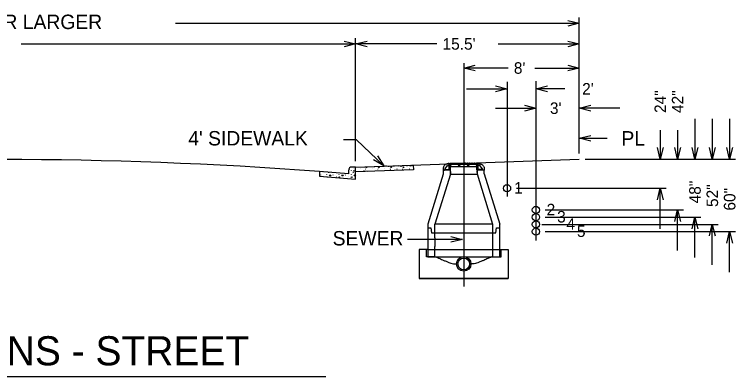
# Model space of a CAD drawing. Extents: x 524397 to 525117, y 3701341 to 3701821.
# Drawn here: x 524804 to 524903.9, y 3701401.1 to 3701451.2 of the extents above; entities that cross this region are included whole.
import ezdxf

# ---------------------------------------------------------------- set-up
doc = ezdxf.new("R2010")
doc.units = 0
doc.layers.add('Level 1', color=7, linetype='Continuous')
doc.layers.add('Level 11', color=7, linetype='Continuous')

msp = doc.modelspace()

# ---------------------------------------------------------------- linework, layer by layer
at = {"layer": 'Level 1'}
msp.add_line((524757.469, 3701401.064), (524847.188, 3701401.064), dxfattribs=at)
at = {"layer": 'Level 11'}
for p, q in [((524882.269, 3701431.982), (524882.269, 3701450.815)), ((524826.327, 3701450.014), (524882.269, 3701450.014)), ((524880.668, 3701450.415), (524882.269, 3701450.014)), ((524882.269, 3701450.014), (524880.668, 3701449.614)), ((524851.288, 3701430.9), (524851.288, 3701447.958)), ((524882.269, 3701431.982), (524882.269, 3701447.958)), ((524804.941, 3701447.157), (524851.288, 3701447.157)), ((524849.687, 3701447.557), (524851.288, 3701447.157)), ((524851.288, 3701447.157), (524849.687, 3701446.757)), ((524851.288, 3701447.157), (524852.889, 3701447.557)), ((524862.537, 3701447.157), (524851.288, 3701447.157)), ((524852.889, 3701446.757), (524851.288, 3701447.157)), ((524871.02, 3701447.157), (524882.269, 3701447.157)), ((524880.668, 3701447.557), (524882.269, 3701447.157)), ((524882.269, 3701447.157), (524880.668, 3701446.757)), ((524866.269, 3701444.489), (524866.269, 3701413.524)), ((524866.269, 3701443.819), (524867.87, 3701444.219)), ((524872.41, 3701443.819), (524866.269, 3701443.819)), ((524867.87, 3701443.418), (524866.269, 3701443.819)), ((524876.128, 3701443.819), (524882.269, 3701443.819)), ((524880.668, 3701444.219), (524882.269, 3701443.819)), ((524882.269, 3701443.819), (524880.668, 3701443.418)), ((524872.269, 3701441.919), (524872.269, 3701426.037)), ((524876.269, 3701441.988), (524876.269, 3701419.918)), ((524866.666, 3701440.933), (524872.269, 3701440.933)), ((524870.668, 3701441.334), (524872.269, 3701440.933)), ((524872.269, 3701440.933), (524870.668, 3701440.533)), ((524876.269, 3701440.933), (524877.87, 3701441.334)), ((524880.272, 3701440.933), (524876.269, 3701440.933)), ((524877.87, 3701440.533), (524876.269, 3701440.933)), ((524870.666, 3701438.254), (524876.269, 3701438.254)), ((524874.668, 3701438.654), (524876.269, 3701438.254)), ((524876.269, 3701438.254), (524874.668, 3701437.854)), ((524882.269, 3701438.254), (524883.87, 3701438.654)), ((524887.873, 3701438.254), (524882.269, 3701438.254)), ((524883.87, 3701437.854), (524882.269, 3701438.254)), ((524898.302, 3701436.785), (524898.302, 3701431.182)), ((524900.703, 3701436.785), (524900.703, 3701431.182)), ((524903.105, 3701436.785), (524903.105, 3701431.182)), ((524893.499, 3701435.185), (524893.499, 3701431.182)), ((524895.9, 3701435.185), (524895.9, 3701431.182)), ((524851.416, 3701433.875), (524849.611, 3701433.875)), ((524855.195, 3701430.264), (524851.416, 3701433.875)), ((524882.269, 3701434.088), (524883.87, 3701434.488)), ((524882.269, 3701434.088), (524886.145, 3701434.088)), ((524883.87, 3701433.688), (524882.269, 3701434.088)), ((524893.499, 3701431.182), (524893.099, 3701432.783)), ((524893.899, 3701432.783), (524893.499, 3701431.182)), ((524895.9, 3701431.182), (524895.5, 3701432.783)), ((524896.301, 3701432.783), (524895.9, 3701431.182)), ((524898.302, 3701431.182), (524897.902, 3701432.783)), ((524898.702, 3701432.783), (524898.302, 3701431.182)), ((524900.703, 3701431.182), (524900.303, 3701432.783)), ((524901.103, 3701432.783), (524900.703, 3701431.182)), ((524903.105, 3701431.182), (524902.704, 3701432.783)), ((524903.505, 3701432.783), (524903.105, 3701431.182)), ((524851.288, 3701430.099), (524882.269, 3701431.182)), ((524855.195, 3701430.264), (524853.761, 3701431.081)), ((524854.314, 3701431.66), (524855.195, 3701430.264)), ((524883.07, 3701431.182), (524894.299, 3701431.182)), ((524883.07, 3701431.182), (524896.701, 3701431.182)), ((524883.07, 3701431.182), (524899.102, 3701431.182)), ((524883.07, 3701431.182), (524901.504, 3701431.182)), ((524883.07, 3701431.182), (524903.905, 3701431.182)), ((524851.288, 3701430.099), (524850.775, 3701430.099)), ((524850.775, 3701430.099), (524850.788, 3701430.099)), ((524850.994, 3701429.886), (524851.008, 3701429.918)), ((524851.288, 3701430.099), (524859.283, 3701430.379)), ((524851.288, 3701428.438), (524851.288, 3701430.099)), ((524851.288, 3701429.439), (524851.288, 3701430.099)), ((524851.921, 3701429.833), (524851.935, 3701429.865)), ((524852.444, 3701430.14), (524852.445, 3701430.124)), ((524852.684, 3701429.833), (524852.698, 3701429.812)), ((524852.698, 3701429.825), (524852.713, 3701429.804)), ((524853.622, 3701429.833), (524853.636, 3701429.865)), ((524854.143, 3701430.156), (524854.147, 3701430.124)), ((524854.386, 3701429.833), (524854.4, 3701429.812)), ((524854.4, 3701429.825), (524854.414, 3701429.804)), ((524855.324, 3701429.833), (524855.338, 3701429.865)), ((524855.845, 3701430.156), (524855.848, 3701430.124)), ((524856.087, 3701429.833), (524856.101, 3701429.812)), ((524856.101, 3701429.825), (524856.116, 3701429.804)), ((524856.702, 3701430.245), (524856.716, 3701430.277)), ((524857.025, 3701429.833), (524857.039, 3701429.865)), ((524857.546, 3701430.156), (524857.55, 3701430.124)), ((524857.789, 3701429.833), (524857.803, 3701429.812)), ((524857.803, 3701429.825), (524857.817, 3701429.804)), ((524858.403, 3701430.245), (524858.417, 3701430.277)), ((524858.727, 3701429.833), (524858.741, 3701429.865)), ((524859.248, 3701430.156), (524859.251, 3701430.124)), ((524859.283, 3701430.379), (524859.306, 3701429.719)), ((524863.604, 3701429.665), (524863.604, 3701429.748)), ((524863.604, 3701429.748), (524863.687, 3701429.748)), ((524863.687, 3701429.748), (524863.688, 3701429.853)), ((524863.687, 3701429.748), (524864.27, 3701429.748)), ((524863.688, 3701429.853), (524864.037, 3701430.29)), ((524864.037, 3701430.29), (524864.27, 3701430.29)), ((524864.27, 3701430.581), (524864.27, 3701430.581)), ((524864.27, 3701430.581), (524864.354, 3701430.581)), ((524864.27, 3701430.29), (524864.27, 3701430.581)), ((524864.27, 3701429.748), (524864.27, 3701430.29)), ((524864.354, 3701430.165), (524864.354, 3701430.581)), ((524864.437, 3701430.165), (524864.354, 3701430.165)), ((524864.395, 3701430.581), (524864.395, 3701430.165)), ((524864.438, 3701430.581), (524864.395, 3701430.581)), ((524864.395, 3701430.581), (524864.438, 3701430.581)), ((524864.395, 3701430.165), (524864.395, 3701430.581)), ((524864.395, 3701430.165), (524868.142, 3701430.165)), ((524864.437, 3701430.165), (524864.395, 3701430.165)), ((524864.437, 3701430.165), (524864.488, 3701430.456)), ((524864.488, 3701430.456), (524864.437, 3701430.165)), ((524864.437, 3701429.665), (524864.437, 3701430.165)), ((524864.438, 3701430.581), (524864.453, 3701430.623)), ((524864.438, 3701430.581), (524864.453, 3701430.623)), ((524864.453, 3701430.623), (524864.515, 3701430.623)), ((524864.453, 3701430.623), (524864.515, 3701430.623)), ((524865.551, 3701430.456), (524864.488, 3701430.456)), ((524865.551, 3701430.456), (524864.488, 3701430.456)), ((524864.53, 3701430.581), (524864.515, 3701430.623)), ((524864.515, 3701430.623), (524864.53, 3701430.581)), ((524864.761, 3701430.581), (524864.53, 3701430.581)), ((524864.53, 3701430.581), (524864.761, 3701430.581)), ((524864.761, 3701430.581), (524864.777, 3701430.623)), ((524864.761, 3701430.581), (524864.777, 3701430.623)), ((524864.777, 3701430.623), (524864.836, 3701430.623)), ((524864.777, 3701430.623), (524864.836, 3701430.623)), ((524864.851, 3701430.581), (524864.836, 3701430.623)), ((524864.836, 3701430.623), (524864.851, 3701430.581)), ((524865.078, 3701430.581), (524864.851, 3701430.581)), ((524864.851, 3701430.581), (524865.078, 3701430.581)), ((524865.078, 3701430.581), (524865.093, 3701430.623)), ((524865.078, 3701430.581), (524865.093, 3701430.623)), ((524865.093, 3701430.623), (524865.16, 3701430.623)), ((524865.093, 3701430.623), (524865.16, 3701430.623)), ((524865.176, 3701430.581), (524865.16, 3701430.623)), ((524865.16, 3701430.623), (524865.176, 3701430.581)), ((524865.405, 3701430.581), (524865.176, 3701430.581)), ((524865.176, 3701430.581), (524865.405, 3701430.581)), ((524865.405, 3701430.581), (524865.42, 3701430.623)), ((524865.405, 3701430.581), (524865.42, 3701430.623)), ((524865.42, 3701430.623), (524865.485, 3701430.623)), ((524865.42, 3701430.623), (524865.485, 3701430.623)), ((524865.5, 3701430.581), (524865.485, 3701430.623)), ((524865.485, 3701430.623), (524865.5, 3701430.581)), ((524865.727, 3701430.581), (524865.5, 3701430.581)), ((524865.5, 3701430.581), (524865.727, 3701430.581)), ((524865.603, 3701430.165), (524865.551, 3701430.456)), ((524865.603, 3701430.165), (524865.551, 3701430.456)), ((524865.686, 3701430.165), (524865.603, 3701430.165)), ((524865.686, 3701430.165), (524865.738, 3701430.456)), ((524865.738, 3701430.456), (524865.686, 3701430.165)), ((524865.727, 3701430.581), (524865.743, 3701430.623)), ((524865.727, 3701430.581), (524865.743, 3701430.623)), ((524866.8, 3701430.456), (524865.738, 3701430.456)), ((524866.8, 3701430.456), (524865.738, 3701430.456)), ((524865.743, 3701430.623), (524865.801, 3701430.623)), ((524865.743, 3701430.623), (524865.801, 3701430.623)), ((524865.816, 3701430.581), (524865.801, 3701430.623)), ((524865.801, 3701430.623), (524865.816, 3701430.581)), ((524866.003, 3701430.581), (524865.816, 3701430.581)), ((524865.816, 3701430.581), (524866.003, 3701430.581)), ((524866.003, 3701430.581), (524866.018, 3701430.623)), ((524866.003, 3701430.581), (524866.018, 3701430.623)), ((524866.018, 3701430.623), (524866.269, 3701430.623)), ((524866.018, 3701430.623), (524866.52, 3701430.623)), ((524866.52, 3701430.623), (524866.269, 3701430.623)), ((524866.536, 3701430.581), (524866.52, 3701430.623)), ((524866.52, 3701430.623), (524866.536, 3701430.581)), ((524866.722, 3701430.581), (524866.536, 3701430.581)), ((524866.536, 3701430.581), (524866.722, 3701430.581)), ((524866.722, 3701430.581), (524866.737, 3701430.623)), ((524866.722, 3701430.581), (524866.737, 3701430.623)), ((524866.795, 3701430.623), (524866.737, 3701430.623)), ((524866.737, 3701430.623), (524866.795, 3701430.623)), ((524866.811, 3701430.581), (524866.795, 3701430.623)), ((524866.795, 3701430.623), (524866.811, 3701430.581)), ((524866.852, 3701430.165), (524866.8, 3701430.456)), ((524866.852, 3701430.165), (524866.8, 3701430.456)), ((524867.038, 3701430.581), (524866.811, 3701430.581)), ((524866.811, 3701430.581), (524867.038, 3701430.581)), ((524866.935, 3701430.165), (524866.852, 3701430.165)), ((524866.935, 3701430.165), (524866.986, 3701430.456)), ((524866.986, 3701430.456), (524866.935, 3701430.165)), ((524868.05, 3701430.456), (524866.986, 3701430.456)), ((524867.831, 3701430.456), (524866.986, 3701430.456)), ((524867.038, 3701430.581), (524867.053, 3701430.623)), ((524867.038, 3701430.581), (524867.053, 3701430.623)), ((524867.118, 3701430.623), (524867.053, 3701430.623)), ((524867.053, 3701430.623), (524867.118, 3701430.623)), ((524867.133, 3701430.581), (524867.118, 3701430.623)), ((524867.118, 3701430.623), (524867.133, 3701430.581)), ((524867.362, 3701430.581), (524867.133, 3701430.581)), ((524867.133, 3701430.581), (524867.362, 3701430.581)), ((524867.362, 3701430.581), (524867.377, 3701430.623)), ((524867.362, 3701430.581), (524867.377, 3701430.623)), ((524867.446, 3701430.623), (524867.377, 3701430.623)), ((524867.377, 3701430.623), (524867.446, 3701430.623)), ((524867.46, 3701430.581), (524867.446, 3701430.623)), ((524867.446, 3701430.623), (524867.46, 3701430.581)), ((524867.687, 3701430.581), (524867.46, 3701430.581)), ((524867.46, 3701430.581), (524867.687, 3701430.581)), ((524867.687, 3701430.581), (524867.702, 3701430.623)), ((524867.687, 3701430.581), (524867.702, 3701430.623)), ((524867.761, 3701430.623), (524867.702, 3701430.623)), ((524867.702, 3701430.623), (524867.761, 3701430.623)), ((524867.776, 3701430.581), (524867.761, 3701430.623)), ((524867.761, 3701430.623), (524867.776, 3701430.581)), ((524868.008, 3701430.581), (524867.776, 3701430.581)), ((524867.776, 3701430.581), (524867.831, 3701430.581)), ((524867.831, 3701430.581), (524867.831, 3701430.456)), ((524867.831, 3701430.581), (524867.831, 3701430.456)), ((524867.955, 3701430.581), (524867.955, 3701430.456)), ((524867.955, 3701430.581), (524868.008, 3701430.581)), ((524867.955, 3701430.456), (524867.955, 3701430.581)), ((524868.05, 3701430.456), (524867.955, 3701430.456)), ((524868.008, 3701430.581), (524868.023, 3701430.623)), ((524868.008, 3701430.581), (524868.023, 3701430.623)), ((524868.085, 3701430.623), (524868.023, 3701430.623)), ((524868.023, 3701430.623), (524868.085, 3701430.623)), ((524868.101, 3701430.165), (524868.05, 3701430.456)), ((524868.101, 3701430.165), (524868.05, 3701430.456)), ((524868.1, 3701430.581), (524868.085, 3701430.623)), ((524868.085, 3701430.623), (524868.1, 3701430.581)), ((524868.142, 3701430.581), (524868.1, 3701430.581)), ((524868.1, 3701430.581), (524868.142, 3701430.581)), ((524868.101, 3701429.665), (524868.101, 3701430.165)), ((524868.101, 3701430.165), (524868.184, 3701430.165)), ((524868.142, 3701430.165), (524868.101, 3701430.165)), ((524868.142, 3701430.581), (524868.142, 3701430.165)), ((524868.142, 3701430.581), (524868.142, 3701430.165)), ((524868.184, 3701430.165), (524868.184, 3701430.581)), ((524868.268, 3701430.581), (524868.184, 3701430.581)), ((524868.268, 3701430.29), (524868.268, 3701430.581)), ((524868.268, 3701429.748), (524868.268, 3701430.29)), ((524868.501, 3701430.29), (524868.268, 3701430.29)), ((524868.851, 3701429.748), (524868.268, 3701429.748)), ((524868.85, 3701429.853), (524868.501, 3701430.29)), ((524868.851, 3701429.748), (524868.85, 3701429.853)), ((524868.934, 3701429.748), (524868.851, 3701429.748)), ((524868.934, 3701429.665), (524868.934, 3701429.748)), ((524850.288, 3701429.175), (524846.288, 3701429.477)), ((524846.288, 3701429.477), (524846.288, 3701428.815)), ((524846.288, 3701428.815), (524851.288, 3701428.438)), ((524846.465, 3701428.983), (524846.479, 3701429.015)), ((524846.753, 3701429.328), (524846.767, 3701429.36)), ((524847.307, 3701429.065), (524847.321, 3701429.097)), ((524847.516, 3701429.328), (524847.53, 3701429.307)), ((524847.53, 3701429.32), (524847.545, 3701429.299)), ((524848.166, 3701428.983), (524848.181, 3701429.015)), ((524848.61, 3701428.756), (524848.625, 3701428.735)), ((524849.008, 3701429.065), (524849.022, 3701429.097)), ((524849.868, 3701428.983), (524849.882, 3701429.015)), ((524850.288, 3701429.637), (524850.288, 3701429.175)), ((524850.312, 3701428.756), (524850.326, 3701428.735)), ((524850.677, 3701429.651), (524850.68, 3701429.619)), ((524850.71, 3701429.065), (524850.724, 3701429.097)), ((524850.919, 3701429.328), (524850.933, 3701429.307)), ((524850.933, 3701429.32), (524850.948, 3701429.299)), ((524859.306, 3701429.719), (524851.288, 3701429.439)), ((524851.633, 3701429.488), (524851.647, 3701429.52)), ((524852.475, 3701429.57), (524852.489, 3701429.602)), ((524853.344, 3701429.511), (524853.349, 3701429.52)), ((524854.176, 3701429.57), (524854.19, 3701429.602)), ((524855.891, 3701429.6), (524855.892, 3701429.602)), ((524863.427, 3701429.132), (524861.276, 3701422.165)), ((524864.426, 3701429.132), (524862.276, 3701422.165)), ((524863.427, 3701429.665), (524863.427, 3701429.132)), ((524864.437, 3701429.665), (524863.427, 3701429.665)), ((524863.427, 3701429.665), (524863.604, 3701429.665)), ((524864.426, 3701429.132), (524864.426, 3701429.665)), ((524864.426, 3701429.499), (524864.426, 3701429.172)), ((524864.426, 3701429.132), (524868.112, 3701429.132)), ((524869.111, 3701429.665), (524868.101, 3701429.665)), ((524868.112, 3701429.665), (524868.112, 3701429.166)), ((524869.111, 3701429.665), (524868.112, 3701429.665)), ((524868.112, 3701429.332), (524868.112, 3701429.505)), ((524868.112, 3701429.166), (524870.271, 3701422.17)), ((524869.111, 3701429.665), (524868.934, 3701429.665)), ((524869.111, 3701429.166), (524869.111, 3701429.665)), ((524869.111, 3701429.166), (524871.271, 3701422.17)), ((524873.57, 3701427.152), (524894.299, 3701427.152)), ((524893.099, 3701425.551), (524893.499, 3701427.152)), ((524893.499, 3701421.548), (524893.499, 3701427.152)), ((524893.499, 3701427.152), (524893.899, 3701425.551)), ((524877.57, 3701424.152), (524896.701, 3701424.152)), ((524895.5, 3701422.551), (524895.9, 3701424.152)), ((524895.9, 3701418.548), (524895.9, 3701424.152)), ((524895.9, 3701424.152), (524896.301, 3701422.551)), ((524877.57, 3701423.152), (524899.102, 3701423.152)), ((524897.902, 3701421.551), (524898.302, 3701423.152)), ((524898.302, 3701417.548), (524898.302, 3701423.152)), ((524898.302, 3701423.152), (524898.702, 3701421.551)), ((524861.276, 3701422.165), (524861.276, 3701421.004)), ((524861.276, 3701421.872), (524861.276, 3701421.67)), ((524870.271, 3701422.169), (524862.276, 3701422.165)), ((524862.276, 3701421.004), (524862.276, 3701422.165)), ((524862.276, 3701421.67), (524862.276, 3701421.872)), ((524870.271, 3701422.17), (524870.271, 3701421.004)), ((524870.271, 3701422.17), (524870.271, 3701421.67)), ((524870.271, 3701421.872), (524870.271, 3701421.67)), ((524870.271, 3701421.872), (524870.271, 3701421.67)), ((524871.271, 3701421.67), (524871.271, 3701422.17)), ((524871.271, 3701421.67), (524871.271, 3701422.17)), ((524871.271, 3701417.672), (524871.271, 3701421.872)), ((524877.07, 3701422.152), (524901.504, 3701422.152)), ((524900.303, 3701420.551), (524900.703, 3701422.152)), ((524900.703, 3701416.548), (524900.703, 3701422.152)), ((524900.703, 3701422.152), (524901.103, 3701420.551)), ((524861.276, 3701421.67), (524861.734, 3701421.67)), ((524861.276, 3701421.67), (524861.734, 3701421.67)), ((524861.276, 3701421.67), (524861.276, 3701420.283)), ((524861.276, 3701421.282), (524861.276, 3701417.672)), ((524861.734, 3701421.67), (524861.818, 3701421.004)), ((524861.734, 3701421.67), (524861.818, 3701421.004)), ((524861.818, 3701421.004), (524862.276, 3701421.004)), ((524861.818, 3701421.004), (524862.276, 3701421.004)), ((524862.276, 3701420.283), (524862.276, 3701421.67)), ((524862.276, 3701421.004), (524870.271, 3701421.004)), ((524862.276, 3701421.004), (524870.271, 3701421.004)), ((524870.271, 3701421.67), (524870.271, 3701417.672)), ((524870.271, 3701421.67), (524870.271, 3701417.672)), ((524870.271, 3701421.004), (524870.729, 3701421.004)), ((524870.271, 3701421.004), (524870.729, 3701421.004)), ((524870.729, 3701421.004), (524870.812, 3701421.67)), ((524870.729, 3701421.004), (524870.812, 3701421.67)), ((524870.812, 3701421.67), (524871.271, 3701421.67)), ((524870.812, 3701421.67), (524871.271, 3701421.67)), ((524870.812, 3701421.67), (524871.271, 3701421.67)), ((524871.271, 3701421.004), (524871.271, 3701421.67)), ((524877.57, 3701421.152), (524903.905, 3701421.152)), ((524902.704, 3701419.551), (524903.105, 3701421.152)), ((524903.105, 3701415.548), (524903.105, 3701421.152)), ((524903.105, 3701421.152), (524903.505, 3701419.551)), ((524866.085, 3701420.08), (524858.467, 3701420.08)), ((524862.276, 3701420.283), (524862.276, 3701419.098)), ((524864.484, 3701420.48), (524866.085, 3701420.08)), ((524866.085, 3701420.08), (524864.484, 3701419.679)), ((524862.276, 3701417.672), (524862.276, 3701419.098)), ((524861.276, 3701418.672), (524860.111, 3701418.672)), ((524860.111, 3701418.672), (524860.111, 3701414.674)), ((524861.11, 3701417.672), (524861.11, 3701418.672)), ((524861.276, 3701418.672), (524871.271, 3701418.672)), ((524871.271, 3701418.672), (524872.437, 3701418.672)), ((524871.437, 3701417.672), (524871.437, 3701418.672)), ((524872.437, 3701418.672), (524872.437, 3701414.674)), ((524861.276, 3701417.672), (524861.11, 3701417.672)), ((524861.276, 3701417.672), (524861.11, 3701417.672)), ((524861.276, 3701417.672), (524862.276, 3701417.672)), ((524862.276, 3701417.672), (524861.276, 3701417.672)), ((524862.276, 3701417.672), (524861.276, 3701417.672)), ((524862.276, 3701417.672), (524870.271, 3701417.672)), ((524870.271, 3701417.672), (524871.271, 3701417.672)), ((524870.271, 3701417.672), (524871.271, 3701417.672)), ((524871.271, 3701417.672), (524871.437, 3701417.672)), ((524872.437, 3701414.674), (524860.111, 3701414.674)), ((524860.111, 3701414.674), (524872.437, 3701414.674))]:
    msp.add_line(p, q, dxfattribs=at)
for points in [[(524850.352, 3701429.845), (524850.42, 3701429.775), (524850.315, 3701429.727)], [(524852.766, 3701430.018), (524852.809, 3701430.107), (524852.88, 3701430.054), (524852.766, 3701430.018)], [(524854.467, 3701430.018), (524854.51, 3701430.107), (524854.581, 3701430.054), (524854.467, 3701430.018)], [(524855.432, 3701430.209), (524855.437, 3701430.244)], [(524855.516, 3701430.247), (524855.436, 3701430.21)], [(524856.169, 3701430.018), (524856.212, 3701430.107), (524856.283, 3701430.054), (524856.169, 3701430.018)], [(524857.134, 3701430.209), (524857.147, 3701430.304)], [(524857.263, 3701430.308), (524857.289, 3701430.28), (524857.137, 3701430.21)], [(524857.87, 3701430.018), (524857.913, 3701430.107), (524857.984, 3701430.054), (524857.87, 3701430.018)], [(524858.835, 3701430.209), (524858.857, 3701430.364)], [(524858.908, 3701430.365), (524858.991, 3701430.28), (524858.839, 3701430.21)], [(524847.317, 3701428.737), (524847.324, 3701428.752), (524847.348, 3701428.735)], [(524847.687, 3701428.887), (524847.783, 3701429.068), (524847.857, 3701428.902), (524847.69, 3701428.887)], [(524848.983, 3701428.664), (524849.026, 3701428.752), (524849.097, 3701428.699), (524848.983, 3701428.664)], [(524849.388, 3701428.887), (524849.484, 3701429.068), (524849.559, 3701428.902), (524849.392, 3701428.887)], [(524850.685, 3701428.664), (524850.727, 3701428.752), (524850.798, 3701428.699), (524850.685, 3701428.664)], [(524851.001, 3701429.513), (524851.044, 3701429.602), (524851.115, 3701429.548), (524851.001, 3701429.513)], [(524851.09, 3701428.887), (524851.186, 3701429.068), (524851.26, 3701428.902), (524851.093, 3701428.887)], [(524851.288, 3701429.487), (524851.309, 3701429.44)], [(524852.909, 3701429.496), (524852.951, 3701429.574), (524852.984, 3701429.498)], [(524854.643, 3701429.556), (524854.652, 3701429.574), (524854.66, 3701429.557)]]:
    msp.add_lwpolyline(points, dxfattribs=at)
for centre, radius in [((524872.269, 3701427.152), 0.5), ((524876.269, 3701424.152), 0.5), ((524876.269, 3701423.152), 0.5), ((524876.269, 3701422.152), 0.5), ((524876.269, 3701421.152), 0.5), ((524866.273, 3701416.673), 0.999), ((524866.273, 3701416.673), 0.814)]:
    msp.add_circle(centre, radius, dxfattribs=at)
for centre, radius, start, end in [((524802.288, 3700846.695), 584.44, 85.68236, 94.31764), ((524850.781, 3701429.605), 0.494, 89.23325, 176.29205)]:
    msp.add_arc(centre, radius, start, end, dxfattribs=at)
for points in [[(524864.27, 3701430.581), (524864.197, 3701430.58), (524864.118, 3701430.57), (524864.049, 3701430.558), (524863.99, 3701430.546), (524863.927, 3701430.518), (524863.868, 3701430.505), (524863.725, 3701430.425), (524863.621, 3701430.339), (524863.53, 3701430.221), (524863.454, 3701430.057), (524863.433, 3701429.824), (524863.427, 3701429.665)], [(524868.268, 3701430.581), (524868.34, 3701430.58), (524868.42, 3701430.57), (524868.489, 3701430.558), (524868.547, 3701430.546), (524868.611, 3701430.518), (524868.67, 3701430.505), (524868.813, 3701430.425), (524868.916, 3701430.339), (524869.008, 3701430.221), (524869.084, 3701430.057), (524869.105, 3701429.824), (524869.111, 3701429.665)], [(524862.276, 3701417.672), (524862.69, 3701417.548), (524863.194, 3701417.296), (524863.509, 3701417.15), (524863.928, 3701417.003), (524864.327, 3701416.814), (524864.664, 3701416.73), (524864.999, 3701416.668), (524865.274, 3701416.673)], [(524870.271, 3701417.672), (524869.857, 3701417.548), (524869.353, 3701417.296), (524869.038, 3701417.15), (524868.618, 3701417.003), (524868.219, 3701416.814), (524867.884, 3701416.73), (524867.547, 3701416.668), (524867.273, 3701416.673)]]:
    msp.add_spline(points, degree=3, dxfattribs=at)

# ---------------------------------------------------------------- texts
at = {"layer": 'Level 1'}
msp.add_text('UTILITY LOCATIONS - STREET', height=4.03623, dxfattribs=at).set_placement((524757.679, 3701402.62))
at = {"layer": 'Level 11'}
for s, height, p in [("80' R.O.W. OR LARGER", 2, (524786.694, 3701449.214)), ("15.5'", 1.601, (524863.337, 3701446.357)), ("8'", 1.601, (524873.21, 3701443.018)), ("2'", 1.601, (524882.673, 3701440.133)), ("3'", 1.601, (524878.21, 3701437.453)), ("4' SIDEWALK", 2, (524828.113, 3701433.085)), ('PL', 2, (524888.115, 3701433.07)), ('1', 1.601, (524873.249, 3701426.408)), ('2', 1.601, (524877.754, 3701423.408)), ('3', 1.601, (524879.204, 3701422.408)), ('4', 1.601, (524880.503, 3701421.408)), ('5', 1.601, (524881.953, 3701420.408)), ('SEWER', 2, (524848.108, 3701419.23))]:
    msp.add_text(s, height=height, dxfattribs=at).set_placement(p)
for s, p in [('24"', (524894.299, 3701437.585)), ('42"', (524896.701, 3701437.585)), ('48"', (524899.102, 3701425.061)), ('52"', (524901.504, 3701424.561)), ('60"', (524903.905, 3701424.061))]:
    msp.add_text(s, height=1.601, rotation=90, dxfattribs=at).set_placement(p)

doc.saveas('drawing.dxf')
